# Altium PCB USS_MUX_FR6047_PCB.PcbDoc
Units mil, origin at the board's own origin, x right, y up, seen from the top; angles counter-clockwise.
Board outline 2070 x 1690 mil, 2 copper layers (Top Layer, Bottom Layer), stack 62 mil thick; 37 components, 16 nets, 76 pads, 4 vias.
Unrouted connection lines stored in the file: 2.
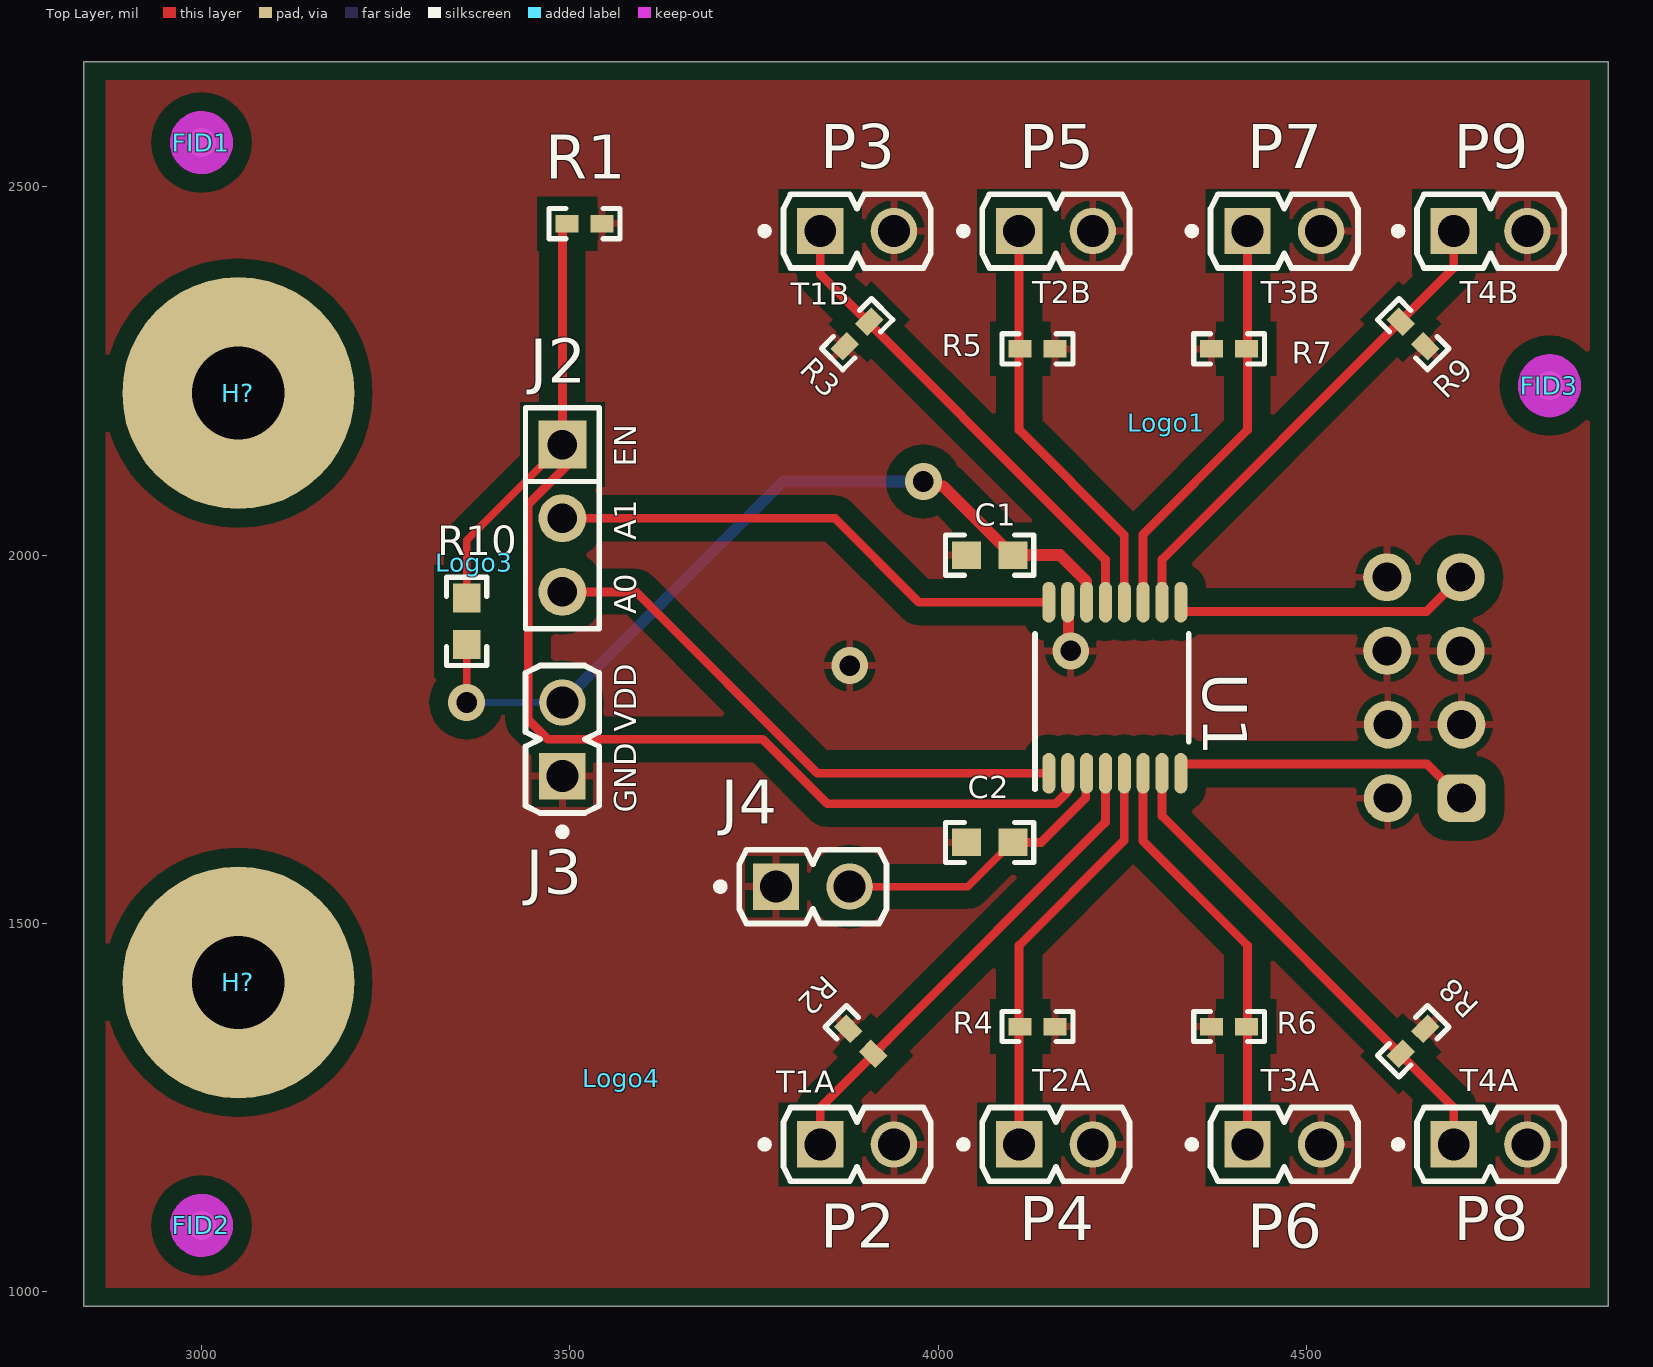
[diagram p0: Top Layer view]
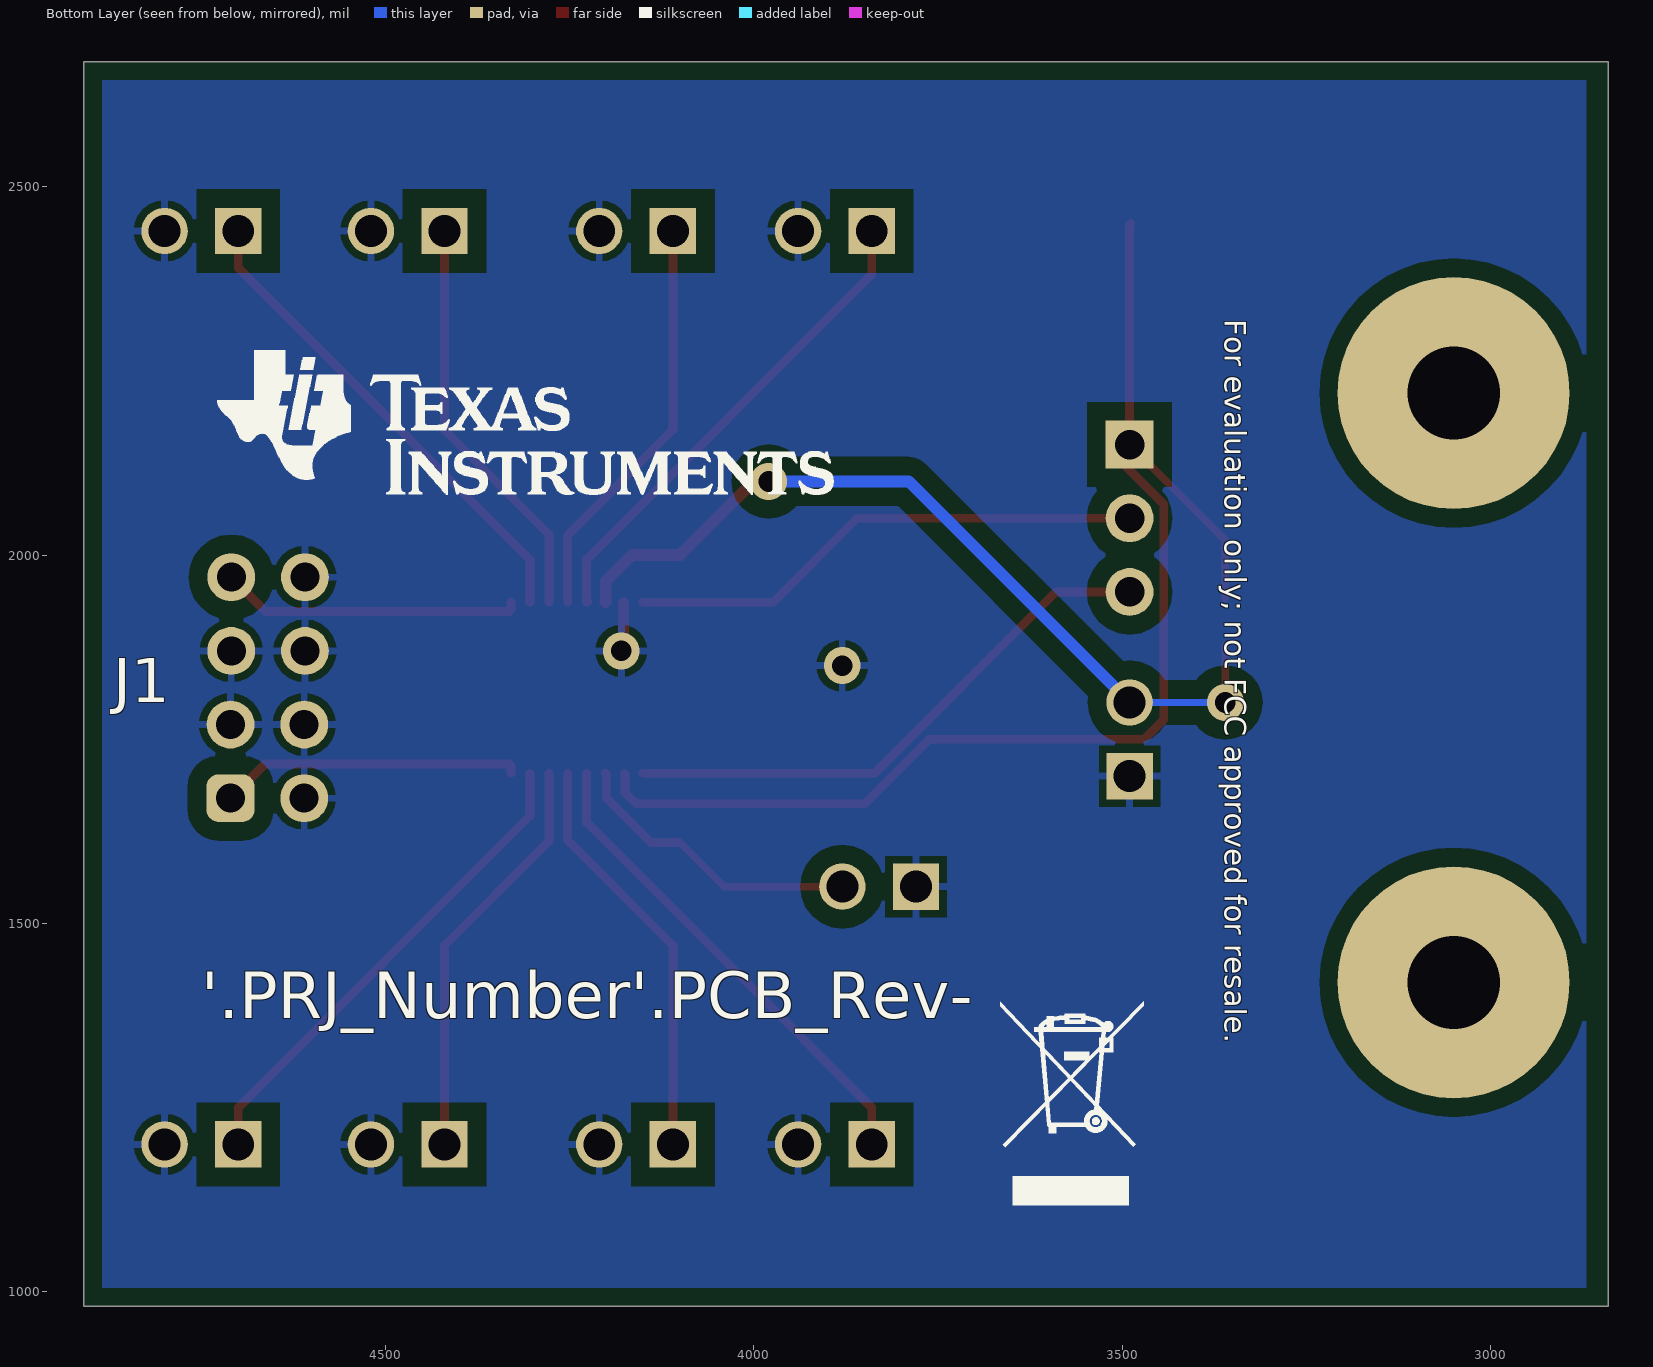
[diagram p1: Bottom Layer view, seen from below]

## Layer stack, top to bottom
Top Solder: solder mask 0.4, Solder Resist, Dk 3.5
Top Layer: signal copper 1.4
Dielectric1: core 59.2, FR-4, Dk 4.8
Bottom Layer: signal copper 1.4
Bottom Solder: solder mask 0.4, Solder Resist, Dk 3.5

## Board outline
2840,980 2840,2670 4910,2670 4910,980

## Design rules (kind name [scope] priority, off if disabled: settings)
AcuteAngle [All] p1: minimum=4.50000000000000E+0001 checktracksonly=FALSE
AssemblyTestPointUsage [All] p1: valid=2
BoardOutlineClearance BoardOutlineClearance_MountingHoles [OnCopper and InComponentClass('Mounting Holes')] p1: gap=40 ignorepadtopadclearanceinfootprint=FALSE
BoardOutlineClearance BoardOutlineClearance_Poly [OnCopper and IsPoly] p2: gap=25 ignorepadtopadclearanceinfootprint=FALSE
BoardOutlineClearance [OnCopper and Not InComponentClass('Logo') and not InComponentClass('FiducialMark') and not InRegion(1000,500,4000,800) and not InPoly] p3: gap=75 ignorepadtopadclearanceinfootprint=FALSE
Clearance Clearance_Keepouts [((IsTrack Or IsArc) And Not InPoly) And IsFree and IsKeepOut vs ((IsTrack Or IsArc) And Not InPoly) And IsFree and IsKeepOut] p1: gap=0 ignorepadtopadclearanceinfootprint=FALSE
Clearance Clearance_Poly [InPolygon] p2: gap=25 ignorepadtopadclearanceinfootprint=FALSE except(0: Arc-Hole Track-Hole SMDPad-Hole THPad-Hole Via-Hole Fill-Hole Poly-Hole Region-Hole Text-Hole)
Clearance Clearance_FiducialMark [IsKeepOut and InComponentClass('FiducialMark') vs IsPad and InComponentClass('FiducialMark')] p3: gap=0 ignorepadtopadclearanceinfootprint=FALSE
Clearance [All] p4: gap=7.87 ignorepadtopadclearanceinfootprint=FALSE except(0: Arc-Hole Track-Hole SMDPad-Hole THPad-Hole Via-Hole Fill-Hole Poly-Hole Region-Hole Text-Hole)
ComponentClearance ComponentClearance_MountingHoles_FiducialMarks [InComponentClass('Mounting Holes') vs InComponentClass('FiducialMark')] p1: gap=50 collisioncheckmode=3 verticalgap=10 showdistances=FALSE
ComponentClearance ComponentClearance_Shunt [InComponentClass('Header') vs InComponentClass('Shunt')] p2: gap=0 collisioncheckmode=3 verticalgap=0 showdistances=FALSE
ComponentClearance ComponentClearance_Logo [InComponentClass('Logo')] p3: gap=50 collisioncheckmode=3 verticalgap=10 showdistances=FALSE
ComponentClearance ComponentClearance_ScrewToNut [(HasFootprint('NY PMS 440 0025 PH')) vs (HasFootprint('Keystone_1902C'))] p4: gap=5 collisioncheckmode=3 verticalgap=10 showdistances=FALSE
ComponentClearance ComponentClearance_MountingHoles [InComponentClass('Mounting Holes')] p5: gap=50 collisioncheckmode=3 verticalgap=100000 showdistances=FALSE
ComponentClearance ComponentClearance_SmallPassives [HasFootprint('0201*') or HasFootprint('0402*') or HasFootprint('0508') or HasFootprint('0603*') or HasFootprint('0612') or HasFootprint('0805*') or HasFootprint('0815*') or HasFootprint('0830*') or HasFootprint('1206*') or HasFootprint('1210*') or HasFootprint('1808*') or HasFootprint('1812*') or HasFootprint('1825*') or HasFootprint('2010*') or HasFootprint('2220*') or HasFootprint('2225*') or HasFootprint('2512*') or HasFootprint('2728*') or HasFootprint('3518*') vs HasFootprint('0201*') or HasFootprint('0402*') or HasFootprint('0508') or HasFootprint('0603*') or HasFootprint('0612') or HasFootprint('0805*') or HasFootprint('0815*') or HasFootprint('0830*') or HasFootprint('1206*') or HasFootprint('1210*') or HasFootprint('1808*') or HasFootprint('1812*') or HasFootprint('1825*') or HasFootprint('2010*') or HasFootprint('2220*') or HasFootprint('2225*') or HasFootprint('2512*') or HasFootprint('2728*') or HasFootprint('3518*')] p6: gap=14.96 collisioncheckmode=3 verticalgap=10 showdistances=FALSE
ComponentClearance ComponentClearance_THtoSMT [IsThruComponent vs IsSMTComponent] p7: gap=40 collisioncheckmode=3 verticalgap=30 showdistances=FALSE
ComponentClearance ComponentClearance_THtoTH [IsThruComponent vs IsThruComponent] p8: gap=30 collisioncheckmode=3 verticalgap=30 showdistances=FALSE
ComponentClearance [All] p9: gap=30 collisioncheckmode=3 verticalgap=10 showdistances=FALSE
DiffPairsRouting [All] p1: maxlimit=100 minlimit=10 mostfreqgap=10 toplayer_minwidth=15 toplayer_maxwidth=15 toplayer_prefwidth=15 bottomlayer_minwidth=15 bottomlayer_maxwidth=15 bottomlayer_prefwidth=15 maxuncoupledlength=1000
FabricationTestPointUsage TestPointUsage [All] p1: valid=2 allowmultiple=FALSE
FabricationTestpoint Testpoint [All] p1: side=3 testpointundercomponent=TRUE minsize=40 maxsize=100 preferedsize=60 minholesize=0 maxholesize=40 preferedholesize=32 testpointgrid=1 allowsidetop=TRUE allowsidebottom=TRUE usegrid=TRUE gridtolerance=0.01
FanoutControl Fanout_LCC [IsLCC] p1: bgadir=Out bgaviamode=Centered fanoutstyle=Auto fanoutdirection=Alternating viagrid=1 // Fanout_LCC (Default Rule)
FanoutControl Fanout_BGA [IsBGA] p2: bgadir=Out bgaviamode=Centered fanoutstyle=Auto fanoutdirection=Alternating viagrid=1 // Fanout_BGA (Default Rule)
FanoutControl Fanout_Default [All] p4: bgadir=Out bgaviamode=Centered fanoutstyle=Auto fanoutdirection=Alternating viagrid=1 // Fanout_Default (Default Rule)
FanoutControl Fanout_Small [(CompPinCount < 5)] p5: bgadir=Out bgaviamode=Centered fanoutstyle=Auto fanoutdirection=OutThenIn viagrid=1 // Fanout_Small (Default Rule)
HoleSize [All] p1: absolutevalues=TRUE maxlimit=251 minlimit=7.87 maxpercent=80.000 minpercent=20.000
MinimumAnnularRing MinimumAnnularRing_ThermalPadVias [IsVia and InAnyComponent] p1: minimumring=5.91
MinimumAnnularRing [All] p2: minimumring=8
MinimumSolderMaskSliver MinimumSolderMaskSliver_Logo [InComponentClass('Logo') vs InComponentClass('Logo')] p1: minsoldermaskwidth=0.7
MinimumSolderMaskSliver [All] p2: minsoldermaskwidth=3.94
PlaneConnect [All] p1: planeconnectstyle=Relief reliefexpansion=10 reliefentries=4 reliefconductorwidth=10 reliefairgap=10
PolygonConnect [All] p1: connectstyle=Relief reliefconductorwidth=10 reliefentries=4 polygonreliefangle="90 Angle" airgapwidth=10
RoutingVias ThermalPadVias [IsVia and InAnyComponent] p1: holewidth=7.87 width=19.68 viastyle="Through Hole" minholewidth=7.87 minwidth=19.68 maxholewidth=12.99 maxwidth=23.62
RoutingVias [All] p2: holewidth=16 width=34 viastyle="Through Hole" minholewidth=7.87 minwidth=26 maxholewidth=40 maxwidth=65
SilkToBoardRegionClearance [Not ((IsComment or IsDesignator) And (Hide <> 'False')) and not InRegion(1000,500,4000,800)] p1:
SilkToSilkClearance SilkToSilkClearance_Pb-FreeLogo [(HasFootprint('Pb-Free_Overlay_Medium') OR HasFootprint('Pb-Free_Overlay_Small')) vs (HasFootprint('Pb-Free_Overlay_Medium') OR HasFootprint('Pb-Free_Overlay_Small'))] p1: silktosilkclearance=0
SilkToSilkClearance [All] p2: silktosilkclearance=4
SilkToSolderMaskClearance SilkToComponentPadClearance [(IsPad or IsFill or IsRegion) and InAnycomponent] p1: minsilkscreentomaskgap=5 clearancetoexposedcopper=TRUE
SilkToSolderMaskClearance "Silk to Solder Mask Opening" [All] p2: minsilkscreentomaskgap=4 clearancetoexposedcopper=FALSE
SolderMaskExpansion [All] p1: expansion=1.97
Width [All] p1: maxlimit=100 minlimit=6 preferedwidth=10 checkconnectedcopper=TRUE
15 further rules are at their usual default settings.

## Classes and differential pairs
component class "Mounting Holes": H?
component class Header: J2
component class USS_MUX_FR6047: 2 ` C1 C2 J1 J2 J3 J4 P2 P3 P4 P5 P6 P7 P8 P9 R1 R2 R3 R4 R5 R6 R7 R8 R9 R10 U1
component class Logo: Logo1
component class USS_MUX_FR6047_Hardware: FID1 FID2 FID3 H? Logo1 Logo3 Logo4 ZZ1 ZZ2 ZZ3 ZZ4
component class FiducialMark: FID1 FID2 FID3
component class AssemblyNote: ZZ1 ZZ2 ZZ3 ZZ4

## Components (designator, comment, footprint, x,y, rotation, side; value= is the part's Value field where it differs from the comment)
C1 "GRM188R61A105KA61D" 0603 4070,2000 r180 top value=1uF
C2 "GRM188R61A105KA61D" 0603 4070,1610 r180 top value=1uF
FID1 "Fiducial" Fiducial10-20 3000,2560 r0 top
FID2 "Fiducial" Fiducial10-20 3000,1090 r0 top
FID3 "Fiducial" Fiducial10-20 4830,2230 r0 top
H? "NY PMS 440 0025 PH" "NY PMS 440 0025 PH" 3050,1420 r0 top
H? "NY PMS 440 0025 PH" "NY PMS 440 0025 PH" 3050,2220 r0 top
J1 "PPPC042LFBN-RC" CONN_PPPC042LFBN-RC 4660,1820 r270 bottom
J2 "PBC03SAAN" PBC03SAAN 3490,2050 r270 top
J3 "613 002 111 21" WE-61300211121_V 3490,1750 r90 top
J4 "613 002 111 21" WE-61300211121_V 3830,1550 r0 top
Logo1 "Texas Instruments" TI_Stacked_Overlay_Small 4310,2180 r180 top
Logo3 "FCC disclaimer" FCC_disclaimer 3370,1990 r90 top
Logo4 "WEEE logo" WEEE_Minimum 3570,1290 r180 top
P2 "613 002 111 21" WE-61300211121_V 3890,1200 r0 top
P3 "613 002 111 21" WE-61300211121_V 3890,2440 r0 top
P4 "613 002 111 21" WE-61300211121_V 4160,1200 r0 top
P5 "613 002 111 21" WE-61300211121_V 4160,2440 r0 top
P6 "613 002 111 21" WE-61300211121_V 4470,1200 r0 top
P7 "613 002 111 21" WE-61300211121_V 4470,2440 r0 top
P8 "613 002 111 21" WE-61300211121_V 4750,1200 r0 top
P9 "613 002 111 21" WE-61300211121_V 4750,2440 r0 top
R1 "ERJ-2GEJ104X" 0402 3520,2450 r180 top value=100k
R2 "ERJ-2GEJ104X" 0402 3895,1340 r315 top value=100k
R3 "ERJ-2GEJ104X" 0402 3890,2300 r45 top value=100k
R4 "ERJ-2GEJ104X" 0402 4135,1360 r180 top value=100k
R5 "ERJ-2GEJ104X" 0402 4135,2280 r180 top value=100k
R6 "ERJ-2GEJ104X" 0402 4395,1360 r0 top value=100k
R7 "ERJ-2GEJ104X" 0402 4395,2280 r0 top value=100k
R8 "ERJ-2GEJ104X" 0402 4645,1340 r225 top value=100k
R9 "ERJ-2GEJ104X" 0402 4645,2300 r135 top value=100k
R10 "MCR03EZPJ000" 0603 3360,1910 r270 top value=0
U1 "TMUX1209PWR" PW0016A_N 4240,1820 r90 top
ZZ1 "This Assembly Note is for PCB labels only" AssemblyNoteLabel 185,3938 r0 top
ZZ2 "These assemblies are ESD sensitive, ESD precautions shall be observed." AssemblyNote 185,3829.11 r0 top
ZZ3 "These assemblies must be clean and free from flux and all contaminants. Use of no clean flux is not acceptable." AssemblyNote 185,3740.56 r0 top
ZZ4 "These assemblies must comply with workmanship standards IPC-A-610 Class 2, unless otherwise specified." AssemblyNote 185,3652 r0 top

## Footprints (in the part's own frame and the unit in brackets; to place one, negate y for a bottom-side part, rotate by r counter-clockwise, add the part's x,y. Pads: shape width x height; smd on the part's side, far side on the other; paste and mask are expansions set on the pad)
0402 [mm] "0402 from SM-752 data"
  rect 0.8x0.6 smd: 1(-0.6,0) 2(0.6,0)
  silkscreen extent -1.22,-0.52 1.22,0.52, body extent -0.55,-0.3 0.55,0.3, height 0.6
0603 [mm] "0603 from SM-752 data"
  rect 1x0.95 smd: 1(-0.8,0) 2(0.8,0)
  silkscreen extent -1.52,-0.69 1.52,0.69, body extent -0.87,-0.47 0.87,0.47, height 1
AssemblyNote [mil] "Assembly Note"
AssemblyNoteLabel [mil] "Assembly Note for PCB Labels"
CONN_PPPC042LFBN-RC [mm] "Sullins socket, 100 mil spacing, 4x2"
  rrect50% 1.65x1.65 hole 1 mask+0: 1(3.81,-1.283)
  round 1.65 hole 1 mask+0: 2(3.81,1.257) 3(1.27,-1.283) 4(1.27,1.257) 5(-1.27,-1.257) 6(-1.27,1.283) 7(-3.81,-1.257) 8(-3.81,1.283)
  body extent -5.33,-2.55 5.33,2.53, height 8.52
FCC_disclaimer [mil]
Fiducial10-20 [mm]
  round 1 smd mask+0.5: 1(0,0)
  Top Layer keep-out circle w1.178: c0,0 r0.5
"NY PMS 440 0025 PH" [mm] "4-40 nylon screw and mounting hole"
  round 8 hole 3.2: 1(0,0)
  body extent -3.3,-3.3 3.3,3.3, height 2.69
PBC03SAAN [mm] "Sullins 100mil, 1x3, 230 mil above insulator"
  rect 1.65x1.65 hole 1.016: 1(-2.54,0)
  round 1.65 hole 1.016: 2(0,0) 3(2.54,0)
  silkscreen extent -3.81,-1.27 3.81,1.27, body extent -3.81,-1.27 3.81,1.27, height 8.38
PW0016A_N [mm] "TSOP, 16-Leads, Body 5x4.4mm, Pitch 0.65mm, IPC Medium Density"
  oval 1.4x0.45 smd: 1(-2.95,2.275) 2(-2.95,1.625) 3(-2.95,0.975) 4(-2.95,0.325) 5(-2.95,-0.325) 6(-2.95,-0.975) 7(-2.95,-1.625) 8(-2.95,-2.275) 9(2.95,-2.275) 10(2.95,-1.625) 11(2.95,-0.975) 12(2.95,-0.325) 13(2.95,0.325) 14(2.95,0.975) 15(2.95,1.625) 16(2.95,2.275)
  silkscreen extent -3.5,-2.55 1.85,2.75, body extent -3.21,-2.5 3.21,2.5, height 1
TI_Stacked_Overlay_Small [mil]
WE-61300211121_V [mm] "Header, 2-Leads, Body 5.08x2.54mm, Pitch 2.54mm"
  rect 1.6x1.6 hole 1.1: 1(-1.27,0)
  round 1.6 hole 1.1: 2(1.27,0)
  silkscreen extent -3.31,-1.27 2.54,1.27, body extent -2.54,-1.27 2.54,1.27, height 8.54
WEEE_Minimum [mil] "WEEElie bin"

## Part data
C1 C2: library part CMP-0007317-5, "CAP, CERM, 1 uF, 10 V, +/- 10%, X5R, 0603", Cap_Case=0603, Manufacturer=MuRata, Supplier Part Number 1=490-1543-1-ND, TempCo=X5R, Tolerance_%=10%, Value1=Unknown, Value2=10V, ValueDisplayed=1uF
FID1 FID2 FID3: library part CMP-0077181-1, "Fiducial mark.  There is nothing to buy or mount.", Manufacturer=N/A
H? H?: library part CMP-0003617-1, "Machine Screw, Round, #4-40 x 1/4, Nylon, Philips panhead", Manufacturer="B&F Fastener Supply", Supplier Part Number 1=H542-ND
J1: library part CMP-0054629-2, "Connector, Receptacle, 100mil, 4x2, Gold plated, TH", Manufacturer="Sullins Connector Solutions", Supplier Part Number 1=S7107-ND
J2: library part CMP-0002334-1, "Header, 100mil, 3x1, Gold, TH", Manufacturer="Sullins Connector Solutions", Supplier Part Number 1=S1011E-03-ND
J3 J4 P2 P3 P4 P5 P6 P7 P8 P9: library part CMP-1712-00002-2, "Male Header, Pitch 2.54 mm, 1 x 2 Position, Height 8.54 mm, Tail Length 3 mm, -40 to 105 degC, RoHS, Bulk"
Logo1: library part CMP-0074838-1, "Texas Instrument Corporate Signature"
Logo3: library part CMP-0074847-1, "FCC_disclaimer"
Logo4: library part CMP-0074769-1
R1 R2 R3 R4 R5 R6 R7 R8 R9: library part CMP-0026995-2, "RES, 100 k, 5%, 0.1 W, AEC-Q200 Grade 0, 0402", Manufacturer=Panasonic, Power_W=100mW, Supplier Part Number 1=P100KJCT-ND, TempCo="200 ppm/C", Tolerance_%=5%, Value2=0.1W, Value_Code=100k
R10: library part CMP-0025883-3, "RES, 0, 5%, 0.1 W, 0603", Manufacturer=Rohm, Power_W=100mW, Supplier Part Number 1=RHM0.0GCT-ND, TempCo="400 ppm/C", Tolerance_%=5%, Value2=0.1W, Value_Code=0000, ValueDisplayed=0
U1: library part CMP-0860324-1, "5-V Bidirectional 4:1, 2-Channel Multiplexer, PW0016A (TSSOP-16)", Alternate Manufacturer="Texas Instruments", Operating Temperature Range="-40 to 125 C", Rating=Catalog
ZZ1: library part CMP-0003616-3
ZZ2: library part CMP-0077236-1
ZZ3: library part CMP-0077237-1
ZZ4: library part CMP-0077238-1

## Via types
v1: diameter 50, hole 28, Top Layer to Bottom Layer, tented both sides, 2 vias
v2: diameter 50, hole 28, Top Layer to Bottom Layer, 2 vias

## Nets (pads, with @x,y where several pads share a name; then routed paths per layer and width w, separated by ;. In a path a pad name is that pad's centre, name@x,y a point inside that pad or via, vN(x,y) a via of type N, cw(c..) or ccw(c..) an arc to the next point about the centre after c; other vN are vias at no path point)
A0: J2.3 U1.1 | length 762.4
  Top Layer w12: J2.3 3590,1950 3836.14,1703.86 U1.1
A1: J2.2 U1.16 | length 707.6
  Top Layer w12: J2.2 3860,2050 3973.86,1936.14 U1.16
CH0: J1.1 U1.8 | length 411.1
  Top Layer w12: U1.8 4329.57,1713.71 4332.21,1716.35 4664.15,1716.35 J1.1
CH1: J1.7 U1.9 | length 410.1
  Top Layer w12: U1.9 4329.57,1926.29 4332.21,1923.65 4663.15,1923.65 J1.7
EN: J2.1 R1.2 R10.1 U1.2 | length 1764.1
  Top Layer w10: R10.1 3360,2020 J2.1
  Top Layer w12: R1.2@3488.5,2450 3490,2448.5 J2.1 ; J2.1@3512.22,2137.78 3443.65,2069.2 3443.65,1776.67 3470.31,1750 3761.89,1750 3849.47,1662.43 4159.85,1662.43 4174.93,1677.51 4174.93,1702.76 U1.2
GND: C1.2 C2.2 J1.2 J1.3 J1.4 J1.5 J1.6 J1.8 J3.1 J4.1 P2.2 P3.2 P4.2 P5.2 P6.2 P7.2 P8.2 P9.2 R1.1 R2.1 R3.1 R4.1 R5.1 R6.1 R7.1 R8.1 R9.1 U1.15 | length 67.8
  Top Layer w12: U1.15 U1.15@4177.12,1935.05 ; v2@4177.12,1872.88 v2(4180,1870)
  Top Layer w15: v2@4177.12,1872.88 U1.15@4177.12,1935.05
  other v2: 3880,1850
NetC2_1: C2.1 J4.2 U1.3 | length 404.2
  Top Layer w10: J4.2 4040.51,1550 4100.51,1610 C2.1
  Top Layer w12: C2.1 4140,1610 4200.52,1670.52 4200.52,1702.76 U1.3
T1A: P2.1 R2.2 U1.4 | length 664.2
  Top Layer w12: P2.1 3840,1250 3916.7,1326.71 3931.28,1341.28 4227.2,1637.21 U1.4
T1B: P3.1 R3.2 U1.13 | length 665.9
  Top Layer w12: P3.1 3839.84,2439.84 3840,2439.68 3840,2381.19 4227.2,1993.98 U1.13 U1.13@4226.11,1937.24
T2A: P4.1 R4.2 U1.5 | length 563
  Top Layer w12: P4.1 4110,1315.51 4110,1330 4110,1470 4252.8,1612.8 U1.5
T2B: P5.1 R5.2 U1.12 | length 563
  Top Layer w12: P5.1 4110,2170 4252.8,2027.2 U1.12
T3A: P6.1 R6.2 U1.6 | length 562.5
  Top Layer w12: U1.6 4278.39,1611.61 4420,1470 P6.1
T3B: P7.1 R7.2 U1.11 | length 562.5
  Top Layer w12: U1.11 4278.39,2028.39 4420,2170 P7.1
T4A: P8.1 R8.2 U1.7 | length 667.9
  Top Layer w12: U1.7 4303.98,1646.02 4700,1250 P8.1
T4B: P9.1 R9.2 U1.10 | length 669.4
  Top Layer w12: U1.10@4305.07,1937.24 U1.10 4303.98,1993.98 4627.5,2317.5 4700,2390 P9.1
VDD: C1.1 J3.2 R10.2 U1.14 | length 1128.7
  Top Layer w10: v1(3360,1800) R10.2
  Top Layer w16: v1(3980,2100) 3986.51,2093.49 4007.02,2093.49 4100.51,2000 C1.1 4165.84,2000 4201.29,1964.56 4201.29,1936.47 U1.14
  Bottom Layer w10: v1(3360,1800) J3.2
  Bottom Layer w16: J3.2 3790,2100 v1(3980,2100)
pads on no net: FID1.1 FID2.1 FID3.1 H?.1

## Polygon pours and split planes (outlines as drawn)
GND on Bottom Layer "Bottom Layer-GND 1" (solid, pour order 4): 2870,2650 2870,1000 4890,1000 4890,2650
GND on Top Layer "Top Layer-No Net" (solid, pour order 9): 2870,2650 2870,1000 4910,1000 4910,2650

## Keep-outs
Keep-Out Layer:
  text ".Layer_Name" at 577,-858.49 h60

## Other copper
Top Layer:
  text ".Layer_Name" at 577,-858.49 h60
Bottom Layer:
  text ".Layer_Name" at 577,-858.49 h60

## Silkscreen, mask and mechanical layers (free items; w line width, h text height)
Top Overlay:
  text "T2B" at 4127.89,2342.11 h30
  text "T3B" at 4437.89,2342.11 h30
  text "T4B" at 4707.89,2342.11 h30
  text "T1B" at 3800,2340 h30
  text "EN" at 3590,2120 h30 r90
  text "A1" at 3590,2020 h30 r90
  text "A0" at 3590,1920 h30 r90
  text "VDD" at 3590,1760 h30 r90
  text "GND" at 3590,1650 h30 r90
  text "T2A" at 4127.89,1272.11 h30
  text "T3A" at 4437.89,1272.11 h30
  text "T4A" at 4707.89,1272.11 h30
  text "T1A" at 3780,1270 h30
  text ".Layer_Name" at 577,-858.49 h60
Bottom Overlay:
  text "'.PRJ_Number'.PCB_Rev-" at 4750,1350 h108.27
  text ".Layer_Name" at 577,-858.49 h60
Top Paste:
  text ".Layer_Name" at 577,-858.49 h60
Bottom Paste:
  text ".Layer_Name" at 577,-858.49 h60
Top Solder:
  text ".Layer_Name" at 577,-858.49 h60
  text ".Layer_Name" at 577,-858.49 h60
Bottom Solder:
  text ".Layer_Name" at 577,-858.49 h60
Drill Guide:
  text ".Layer_Name" at 577,-858.49 h60
M1 Board Outline:
  the board outline again, w10
  text ".Layer_Name" at 577,-858.49 h60
M2 Board Dimensions:
  rectangle: 0,-275 125,-150
  rectangle: 125,-400 500,-275
  lines w7: 0,-275 1000,-275 ; 125,-400 125,-150 ; 250,-400 250,-150 ; 500,-400 500,-150 ; 750,-400 750,-150 ; 0,-400 1000,-400 1000,-150 0,-150 0,-400
  text ".Layer_Name" at 577,-858.49 h60
M3 3D STEP Top:
  text ".Layer_Name" at 577,-858.49 h60
M4 3D STEP Bottom:
  text ".Layer_Name" at 577,-858.49 h60
M5 Assembly Top:
  lines w10: -292,-930.17 6308,-930.17 ; -292,-726.83 6310,-726.83 ; -292,-523.5 -292,-1133.5 3713,-1133.5 6310,-1133.5 6310,-523.5 -291.5,-523.5 -291.5,-1133.5 1284,-1133.5 ; 2173,-1133.5 2173,-523.5 ; 3440,-726.83 3440,-523.5 ; 4280,-726.83 4280,-523.5 ; 4902,-1140 4902,-937.17
  text "COMPONENTS MARKED 'DNP' SHOULD NOT BE POPULATED." at 1153.5,-318.5 h60
  text "ASSEMBLY VARIANT:" at 1153,-434 h60
  text ".VariantName" at 2189,-434 h60
  text "PCB VIEWED FROM TOP SIDE" at -228.5,-655.67 h60
  text "BOARD #:" at 2248,-655.67 h60
  text ".PRJ_Number" at 2793.5,-655.67 h60
  text "REV:" at 3638,-655.67 h60
  text ".PCB_Rev" at 3929.5,-655.67 h60
  text "SVN REV:" at 4476,-655.67 h60
  text ".VersionControl_RevNumber" at 4982,-655.67 h60
  text "TID #:" at 2248,-859 h60
  text ".TID" at 2793.5,-859 h60
  text "PLOT NAME =" at -228.5,-1064.34 h60
  text ".plot_File_Name" at 577,-1064.34 h60
  text "GENERATED    :" at 2250,-1064.34 h60
  text ".Print_Date" at 3119.5,-1064.34 h60
  text ".Print_Time" at 3848.5,-1064.34 h60
  text "TEXAS INSTRUMENTS" at 5113,-1064.34 h60
M6 Assembly Bottom:
  lines w10: -292.5,-727.33 6309.5,-727.33 ; -290.5,-930.67 6309.5,-930.67 ; 1115.5,-1140.5 1115.5,-937.67 ; 1737.5,-727.33 1737.5,-524 ; 2577.5,-727.33 2577.5,-524 ; 3844.5,-1134 3844.5,-524 ; 4733.5,-1134 6309,-1134 6309,-524 -292.5,-524 -292.5,-1134 2304.5,-1134 6309.5,-1134 6309.5,-524
  text "COMPONENTS MARKED 'DNP' SHOULD NOT BE POPULATED." at 6102,-318 h60
  text ".VariantName" at 5058,-434 h60
  text "ASSEMBLY VARIANT:" at 6097,-434 h60
  text ".VersionControl_RevNumber" at 1035.5,-656.17 h60
  text "SVN REV:" at 1541.5,-656.17 h60
  text ".PCB_Rev" at 2088,-656.17 h60
  text "REV:" at 2379.5,-656.17 h60
  text ".PRJ_Number" at 3224,-656.17 h60
  text "BOARD #:" at 3769.5,-656.17 h60
  text "PCB VIEWED FROM BOTTOM SIDE" at 6246,-656.17 h60
  text ".TID" at 3224,-859.5 h60
  text "TID #:" at 3769.5,-859.5 h60
  text "TEXAS INSTRUMENTS" at 904.5,-1064.84 h60
  text ".Print_Time" at 2169,-1064.84 h60
  text ".Print_Date" at 2898,-1064.84 h60
  text "GENERATED    :" at 3767.5,-1064.84 h60
  text ".plot_File_Name" at 5440.5,-1064.84 h60
  text "PLOT NAME =" at 6246,-1064.84 h60
M9 Title Sheet:
  drawing of 57 lines, arcs and shapes, not listed
  text "1" at 739.84,8036.5 h70
  text "2" at 3235.5,8036.5 h70
  text "3" at 5724.84,8036.5 h70
  text "4" at 8231.51,8036.5 h70
  text "5" at 10730.5,8036.5 h70
  text "6" at 13235.5,8036.5 h70
  text "A" at -416.5,6893.5 h70
  text "A" at 14383.5,6893.5 h70
  text "B" at -416.5,4513.5 h70
  text "B" at 14383.5,4513.5 h70
  text "C" at -416.5,2138.5 h70
  text "C" at 14383.5,2138.5 h70
  text "PROJECT TITLE:" at 11343.5,277.5 h45
  text ".PRJ_Title" at 11393.5,144.17 h70
  text "DESIGNED FOR:" at 11343.5,-23.5 h45
  text ".PRJ_Customer" at 11393.5,-163.5 h70
  text "D" at -416.5,-231.5 h70
  text "D" at 14383.5,-231.5 h70
  text "FILE NAME:" at 11343.5,-323.5 h45
  text ".PCB_File_Name_No_Path" at 11393.5,-443.5 h70
  text "Texas Instruments (TI) and/or its licensors do not warrant the accuracy or completeness of this specification" at 6374,-605.34 h45
  text "ENGINEER:" at 11343.5,-613.5 h45
  text "LAYOUT BY:" at 12848.5,-613.5 h45
  text "or any information contained therein. TI and/or its licensors do not warrant that this design will meet" at 6329.01,-718 h45
  text ".PRJ_Engineer" at 11393.5,-768.49 h70
  text ".PCB_Layout" at 12899,-768.49 h70
  text "the specifications, will be suitable for your application or fit for any particular purpose, or will operate in" at 6329.01,-830.67 h45
  text ".Layer_Name" at 577,-858.49 h60
  text "ALTIUM DESIGNER VERSION:" at 12848.5,-923.5 h45
  text "an implementation. TI and/or its licensors do not warrant that the design is production worthy. You should" at 6329.01,-943.33 h45
  text "completely validate and test your design implementation to confirm the system functionality for your application." at 6374,-1056 h45
  text ".print_Scale" at 11393.5,-1056.83 h70
  text ".Application_BuildNumber" at 12899,-1056.83 h70
  text "1" at 739.84,-1263.5 h70
  text "2" at 3235.5,-1263.5 h70
  text "3" at 5724.84,-1263.5 h70
  text "4" at 8231.51,-1263.5 h70
  text "5" at 10730.5,-1263.5 h70
  text "6" at 13235.5,-1263.5 h70
M10 Fab Notes:
  drawing of 189 lines, arcs and shapes, not listed
  text "DESIGN INFORMATION" at 12382.02,6356.17 h60
  text "MIN. TRACK WIDTH:" at 11737.46,6224.05 h60
  text "8" at 12833.7,6224.05 h60
  text "MIL" at 12988.46,6224.05 h60
  text "MIN. CLEARANCE:" at 11737.46,6099.92 h60
  text "0.2" at 12773.7,6099.93 h60
  text "mm" at 12988.46,6099.92 h60
  text "MIN. VIA PAD SIZE:" at 11737.46,5975.8 h60
  text "24" at 12803.71,5975.8 h60
  text "MIL" at 12988.46,5975.8 h60
  text "0.05mm (2MIL)" at 12432.46,5845.9 h60
  text "MINIMUM ANNULAR RING" at 11408.23,5837.67 h60
  text "EXTERNAL" at 13140.46,5837.67 h60
  text "PER" at 11608.23,5727.55 h60
  text "IPC-D-275 CLASS 2 LEVEL C" at 11828.23,5727.54 h60
  text "MIL, HOLES" at 13316.46,5627.07 h60
  text "+/-" at 12924,5618.48 h60
  text "+/-" at 13778,5618.48 h60
  text "REGISTRATION TOLERANCES:" at 11408.23,5617.42 h60
  text "METAL" at 12608,5617.42 h60
  text "5" at 13184.2,5617.42 h60
  text "3" at 14017.2,5617.42 h60
  text "MIL" at 14133.46,5617.42 h60
  text "HOLE SIZE TOLERANCE (UNLESS OTHERWISE SPECIFIED):" at 11408.23,5519.1 h60
  text "+/-" at 13778,5516.23 h60
  text "3" at 14017.2,5515.17 h60
  text "MIL" at 14133.46,5515.17 h60
  text "MATERIAL:" at 11333.46,5377.52 h60
  text "FR-4 High Tg" at 12319.9,5249 h60
  text "X" at 12175.46,5241.01 h60
  text "FR-408" at 11754.46,5236.49 h60
  text "OTHER" at 13242.46,5236.49 h60
  text "62 MIL (1.6mm) +/-10%" at 12074.56,5093.46 h60
  text "X" at 11954.46,5091.01 h60
  text "THICKNESS:" at 11408.23,5085.24 h60
  text "OTHER" at 13359.46,5085.24 h60
  text "TOLERANCE:" at 11408.23,4946.92 h60
  text "X" at 12256.46,4946.92 h60
  text "ANSI IPC-6012 TYPE 3 CLASS 2" at 12434.48,4946.92 h60
  text "OTHER +/-" at 12434.46,4802.73 h60
  text "BOW & TWIST:" at 11408.23,4657.54 h60
  text "X" at 12256.46,4657.54 h60
  text "ANSI IPC-6012 TYPE 3 CLASS 2" at 12434.48,4657.54 h60
  text "OTHER +/-" at 12434.46,4510.85 h60
  text "DRILLING:" at 11333.46,4380.23 h60
  text "NC_DRILL FILES" at 13094.46,4275.04 h60
  text "REFERENCE:" at 11408.23,4271.1 h60
  text "X" at 12065.46,4271.01 h60
  text "AS SHOWN" at 12243.46,4271.1 h60
  text "X" at 12966.46,4271.1 h60
  text "OTHER" at 13392.46,4128.85 h60
  text "PTH COPPER THICKNESS:" at 11407.91,4125.32 h60
  text "X" at 12547.14,4125.32 h60
  text "20-30 um" at 12675.14,4125.32 h60
  text "BOARD FINISH:" at 11333.46,3977.73 h60
  text "SILKSCREEN:" at 11488.68,3867.6 h60
  text "X" at 12446.46,3867.6 h60
  text "TOP" at 12563.46,3867.6 h60
  text "X" at 12956.46,3867.6 h60
  text "BOTTOM" at 13074.46,3867.6 h60
  text "SILKSCREEN COLOR:" at 11488.68,3712.41 h60
  text "X" at 12445.46,3712.41 h60
  text "WHITE" at 12563.46,3712.41 h60
  text "OTHER" at 13074.46,3712.41 h60
  text "X" at 12576.46,3568.96 h60
  text "GREEN" at 12694.46,3568.96 h60
  text "OTHER" at 13312.46,3568.96 h60
  text "SOLDER RESIST COLOR:" at 11488.68,3562.1 h60
  text "X" at 12576.46,3414.71 h60
  text "MATTE" at 12694.46,3414.71 h60
  text "SEMI-GLOSS" at 13312,3414.07 h60
  text "IMMERSION GOLD (ENIG)" at 12394.46,3241.94 h60
  text "ENEPIG" at 13732,3234.72 h60
  text "SURFACE FINISH:" at 11333.46,3233.72 h60
  text "X" at 12216.46,3233.72 h60
  text "IMM. TIN/SILVER OR EQUIV" at 11663,3096.4 h60
  text "OTHER" at 13094.46,3092.47 h60
  text "ARRAY/PANEL:" at 11333.46,2937.09 h60
  text "CUT AND TRIM PER M1 BOARD OUTLINE" at 12394.46,2928.87 h60
  text "N.C. ROUTE" at 12394.46,2792.9 h60
  text "X" at 13082.46,2792.9 h60
  text "V. SCORE" at 13260.46,2792.9 h60
  text "CERTIFICATION:" at 11333.46,2663.77 h60
  text "MATERIALS AND WORKMANSHIP FOR ALL PCBS" at 12058.46,2663.77 h60
  text "TO MEET OR EXCEED THE REQUIREMENTS OF:" at 12058.46,2569.71 h60
  text "X" at 11695.97,2441.08 h60
  text "ANSI IPC-A-600F CLASS ->" at 11823.96,2441.08 h60
  text "X" at 13471.97,2441.08 h60
  text "2" at 13581.96,2441.08 h60
  text "1" at 13266.96,2439.58 h60
  text "3" at 13935.96,2439.58 h60
  text "X" at 12507.97,2293.39 h60
  text "RoHS" at 12635.96,2293.39 h60
  text "OTHER" at 13280.36,2293.39 h60
  text "PER ORDER" at 13677.42,2293.39 h60
  text "ALL BOARDS MUST MEET OR EXCEED UL94-V0 REQUIREMENTS." at 11361,2139.57 h60
  text "PCB MUST BEAR THE UL94V-0 UL REGISTERED MATERIAL ID NUMBER" at 11361,2023.5 h60
  text "ADDITIONAL REQUIREMENTS:" at 11333.46,1854.08 h60
  text "MICROSECTION:" at 11408.23,1746.95 h60
  text "YES" at 12313.96,1746.95 h60
  text "REQUIRED" at 13175.46,1602.62 h60
  text "BARE BOARD ELEC. TEST:" at 11408.23,1599.76 h60
  text "NONE" at 12713.96,1599.76 h60
  text "X" at 13057.46,1599.76 h60
  text "PER ORDER" at 13767.46,1599.76 h60
  text "XX MIL VIAS REQUIRE NON-CONDUCTIVE FILL AND PLANARIZE" at 11576.38,1394.82 h59
  text "XX MIL VIAS REQUIRE CONDUCTIVE FILL AND PLANARIZE" at 11584.38,1290.84 h60
  text "OUTER XX MIL TRACES REQUIRE 50 OHM SINGLE-ENDED IMPEDANCE" at 11583.39,1127.46 h58
  text "LAYER 2 & 3 (INNER LAYERS) XX MIL WIDE, XX MIL SPACE / TRACES REQUIRE 100 OHM DIFFERENTIAL IMPEDANCE" at 11575.39,891.74 h60
  text ".Layer_Name" at 577,-858.49 h60
M11 Gerber Information:
  lines w10: -292,-930.17 6308,-930.17 ; -292,-726.83 6310,-726.83 ; -292,-523.5 -292,-1133.5 3713,-1133.5 6310,-1133.5 6310,-523.5 -291.5,-523.5 -291.5,-1133.5 1284,-1133.5 ; 2173,-1133.5 2173,-523.5 ; 3440,-726.83 3440,-523.5 ; 4280,-726.83 4280,-523.5 ; 4902,-1140 4902,-937.17
  text "ALL ARTWORK VIEWED FROM TOP SIDE" at -228.5,-655.67 h60
  text "BOARD #:" at 2248,-655.67 h60
  text ".PRJ_Number" at 2793.5,-655.67 h60
  text "REV:" at 3638,-655.67 h60
  text ".PCB_Rev" at 3929.5,-655.67 h60
  text "SVN REV:" at 4476,-655.67 h60
  text ".VersionControl_RevNumber" at 4982,-655.67 h60
  text "LAYER NAME =" at -228.5,-858.49 h60
  text "TID #:" at 2248,-859 h60
  text ".TID" at 2793.5,-859 h60
  text "PLOT NAME =" at -228.5,-1064.34 h60
  text ".plot_File_Name" at 577,-1064.34 h60
  text "GENERATED    :" at 2250,-1064.34 h60
  text ".Print_Date" at 3119.5,-1064.34 h60
  text ".Print_Time" at 3848.5,-1064.34 h60
  text "TEXAS INSTRUMENTS" at 5113,-1064.34 h60
M12 Stackup:
  drawing of 191 lines, arcs and shapes, not listed
  text "Layer" at 9807.84,7740 h60
  text "Name" at 10217.76,7740 h60
  text "Material" at 11147.5,7740 h60
  text "Thickness" at 12007.27,7740 h60
  text "Constant" at 12657.1,7740 h60
  text "Board Layer Stack" at 13226.96,7740 h60
  text "Top Overlay" at 10217.76,7620 h60
  text "Top Solder" at 10217.76,7500 h60
  text "Solder Resist" at 11147.5,7500 h60
  text "0.40mil" at 12007.27,7500 h60
  text "3.5" at 12657.1,7500 h60
  text "1" at 9807.84,7380 h60
  text "Top Layer" at 10217.76,7380 h60
  text "Copper" at 11147.5,7380 h60
  text "1.40mil" at 12007.27,7380 h60
  text "Dielectric1" at 10217.76,7260 h60
  text "FR-4" at 11147.5,7260 h60
  text "59.20mil" at 12007.27,7260 h60
  text "4.8" at 12657.1,7260 h60
  text "2" at 9807.84,7140 h60
  text "Bottom Layer" at 10217.76,7140 h60
  text "Copper" at 11147.5,7140 h60
  text "1.40mil" at 12007.27,7140 h60
  text "Bottom Solder" at 10217.76,7020 h60
  text "Solder Resist" at 11147.5,7020 h60
  text "0.40mil" at 12007.27,7020 h60
  text "3.5" at 12657.1,7020 h60
  text "Bottom Overlay" at 10217.76,6900 h60
  text ".Layer_Name" at 577,-858.49 h60
M13 Component Bodies Top:
  text ".Layer_Name" at 577,-858.49 h60
M14 Component Bodies Bottom:
  text ".Layer_Name" at 577,-858.49 h60
M15 Courtyards Top:
  text ".Layer_Name" at 577,-858.49 h60
M16 Courtyards Bottom:
  text ".Layer_Name" at 577,-858.49 h60
Drill Drawing:
  circle w10: c5363.72,3290.28 r27.63
  lines w10: 5336.09,2779.19 5349.9,2779.19 5363.72,2765.38 5377.53,2779.19 5391.34,2779.19 5377.53,2793 5391.34,2806.82 5377.53,2806.82 5363.72,2820.63 5349.9,2806.82 5336.09,2806.82 5349.9,2793 5336.09,2779.19 ; 5336.09,2889.7 5391.34,2889.7 5391.34,2944.95 5336.09,2944.95 5336.09,2889.7 ; 5336.09,3014.02 5363.72,3027.83 5391.34,3014.02 5377.53,3041.64 5391.34,3069.27 5363.72,3055.46 5336.09,3069.27 5349.9,3041.64 5336.09,3014.02 ; 5336.09,3193.59 5391.34,3193.59 5363.72,3138.34 5336.09,3193.59
  lines w12: 5286,2728.08 8517.49,2728.08 ; 5286,3349.68 8517.49,3349.68 ; 5623.86,2603.76 5623.86,3474 ; 5955.86,2603.76 5955.86,3474 ; 6592.43,2603.76 6592.43,3474 ; 6851.57,2603.76 6851.57,3474 ; 7226.72,2603.76 7226.72,3474 ; 7951.05,2603.76 7951.05,3474 ; 5286,2603.76 8517.49,2603.76 8517.49,3474 5286,3474 5286,2603.76
  text "Symbol" at 5360.59,3386.98 h72
  text "Quantity" at 5661.16,3386.98 h72
  text "Finished Hole Size" at 5993.16,3386.98 h72
  text "Plated" at 6629.72,3386.98 h72
  text "Hole Type" at 6888.86,3386.98 h72
  text "Drill Layer Pair" at 7264.02,3386.98 h72
  text "Hole Tolerance" at 7988.35,3386.98 h72
  text "3" at 5661.16,3262.66 h60
  text "28.00mil (0.711mm)" at 5993.16,3262.66 h60
  text "PTH" at 6629.72,3262.66 h60
  text "Round" at 6888.86,3262.66 h60
  text "Top Layer - Bottom Layer" at 7264.02,3262.66 h60
  text "8" at 5661.16,3138.34 h60
  text "39.37mil (1.000mm)" at 5993.16,3138.34 h60
  text "PTH" at 6629.72,3138.34 h60
  text "Round" at 6888.86,3138.34 h60
  text "Top Layer - Bottom Layer" at 7264.02,3138.34 h60
  text "3" at 5661.16,3014.02 h60
  text "40.00mil (1.016mm)" at 5993.16,3014.02 h60
  text "PTH" at 6629.72,3014.02 h60
  text "Round" at 6888.86,3014.02 h60
  text "Top Layer - Bottom Layer" at 7264.02,3014.02 h60
  text "20" at 5661.16,2889.7 h60
  text "43.31mil (1.100mm)" at 5993.16,2889.7 h60
  text "PTH" at 6629.72,2889.7 h60
  text "Round" at 6888.86,2889.7 h60
  text "Top Layer - Bottom Layer" at 7264.02,2889.7 h60
  text "2" at 5661.16,2765.38 h60
  text "125.98mil (3.200mm)" at 5993.16,2765.38 h60
  text "PTH" at 6629.72,2765.38 h60
  text "Round" at 6888.86,2765.38 h60
  text "Top Layer - Bottom Layer" at 7264.02,2765.38 h60
  text "36 Total" at 5661.16,2641.06 h60
  text ".Layer_Name" at 577,-858.49 h60
M17 Embedded Cavity:
  text ".Layer_Name" at 577,-858.49 h60
M18 Embedded Assembly:
  text ".Layer_Name" at 577,-858.49 h60
M19 Embedded Keepout:
  text ".Layer_Name" at 577,-858.49 h60

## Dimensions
2444.01,945.94 to 2404.01,2635.94 on M2 Board Dimensions
2890,900 to 4950,950 on M2 Board Dimensions
0,-400 to 1000,-400 on M2 Board Dimensions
